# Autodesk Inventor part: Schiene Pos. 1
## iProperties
Created: 2009-11
Part Number: Schiene Pos. 1
Document SubType Name: Modeling
Designer: user
Author: user
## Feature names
1. Extrusion1
2. Extrusion2
3. Bohrung1 [Hole]
4. Bohrung2 [Hole]
5. Extrusion3
